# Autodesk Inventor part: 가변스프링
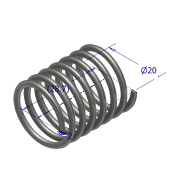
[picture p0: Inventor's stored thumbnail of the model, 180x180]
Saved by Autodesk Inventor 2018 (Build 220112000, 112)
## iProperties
Created: 2020-01
Part Number: 가변스프링
Material: 스테인레스 스틸
Document SubType Name: Modeling
Designer: Administrator
Density: 8 g/cm^3
Appearance: 반연마
Mass: 10.8825 g
Surface Area: 27.5643 cm^2
Volume: 1.36032 cm^3
Author: Administrator
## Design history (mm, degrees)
sketch "스케치1"
  geometry: L1 (0, 0)-(10, 0); L2 (10, 0)-(10, 28.7); L3 (10, 28.7)-(0, 28.7); L4 (0, 28.7)-(0, 0); C1 r 1 at (10, 0)
  constraints: 8 end point, 2 parallel, 1 centre point, 1 coincident, 1 horizontal, 1 perpendicular
  dimensions: "d0" = 2 diameter of C1; "d1" = 28.7 distance of L3.end L1.start (derived); "d2" = 20 diameter of L2 L4
feature "코일1" sketch "스케치1" pitch "d3" = 10; turns "d5" = 7; dims "d4" = 28.7 (= d1), "d6" = 0, angle "d7" = 90 deg, angle "d8" = 90 deg, "d9" = 0, "d10" = 0
sketch "스케치2"
  geometry: L1 (-9, 0)-(-11, 0) reference; 1 further point
  constraints: 1 horizontal alignment
extrude "돌출1" cut sketch "스케치2" extent not by distance; stored distance "d11" = 10; taper "d12" = 0 deg
node "작업 평면1"
sketch "스케치3"
  geometry: L1 (-1, 0)-(1, 0) reference; 1 further point
  constraints: 1 horizontal alignment
extrude "돌출2" cut sketch "스케치3" extent not by distance; stored distance "d14" = 10; taper "d15" = 0 deg
node "솔리드1"
node "절단 모서리 투영1"
node "절단 모서리 투영2"
other parameters: "d13" = 90 deg
